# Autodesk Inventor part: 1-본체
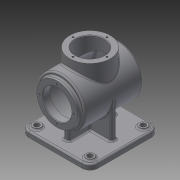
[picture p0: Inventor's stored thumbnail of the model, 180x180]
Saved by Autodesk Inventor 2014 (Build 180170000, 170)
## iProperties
Created: 2015-07
Part Number: 1-본체
Material: 일반
Document SubType Name: Modeling
Designer: Owner
Density: 1 g/cm^3
Appearance: 기본값
Author: Owner
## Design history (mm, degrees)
sketch "스케치1"
  geometry: C1 r 45 at (0, 0); 1 further point
  constraints: 1 centre point, 1 coincident
  dimensions: "d0" = 90 diameter of C1
extrude "돌출1" new body sketch "스케치1" stored distance "d1" = 110; taper "d2" = 0 deg
sketch "스케치2"
  geometry: C1 r 45 at (0, 0) reference; C2 r 38 at (0, 0)
  constraints: 1 centre point, 1 coincident
  dimensions: "d3" = 76 diameter of C2
extrude "돌출2" join sketch "스케치2" distance "d4" = 7; taper "d5" = 0 deg
node "작업 평면1"
sketch "스케치3"
  geometry: L1 (-65, 65)-(65, 65); L2 (65, 65)-(65, -65); L3 (65, -65)-(-65, -65); L4 (-65, -65)-(-65, 65); 3 further points
  constraints: 8 end point, 2 midpoint, 2 parallel, 1 horizontal, 1 horizontal alignment, 1 perpendicular, 1 vertical alignment
  dimensions: "d7" = 130 distance of L2.end L3.end; "d8" = 130 distance of L3.end L1.start
extrude "돌출3" join sketch "스케치3" distance "d9" = 10; taper "d10" = 0 deg
sketch "스케치4"
  geometry: L1 (-65, 65)-(-65, -65) reference; L2 (-45, 5)-(-5, 5); L3 (-5, 5)-(-5, 45); L4 (-5, 45)-(5, 45); L5 (5, 45)-(5, 5); L6 (5, 5)-(45, 5); L7 (45, 5)-(45, -5); L8 (45, -5)-(5, -5); L9 (5, -5)-(5, -45); L10 (5, -45)-(-5, -45); L11 (-5, -45)-(-5, -5); L12 (-5, -5)-(-45, -5); L13 (-45, -5)-(-45, 5); 4 further points
  constraints: 24 end point, 8 parallel, 7 equal length, 3 midpoint, 2 collinear, 2 perpendicular, 2 vertical alignment, 1 horizontal alignment
  dimensions: "d11" = 10 distance of L3.end L4.end; "d12" = 90 distance between parallel lines of L7 L13
extrude "돌출4" join sketch "스케치4" stored distance "d13" = 10; taper "d14" = 0 deg
sketch "스케치5"
  geometry: C1 r 7.5 at (-50, 50); C2 r 7.5 at (-50, -50); C3 r 7.5 at (50, -50); C4 r 7.5 at (50, 50); 1 further point
  constraints: 4 centre point, 2 horizontal alignment, 2 vertical alignment
  dimensions: "d15" = 15 diameter of C1; "d16" = 15 diameter of C2; "d17" = 15 diameter of C3; "d18" = 15 diameter of C4; "d19" = 100 distance of C4.centre C1.centre; "d20" = 50 horizontal distance of C4.centre point (0, 0); "d21" = 100 distance of C2.centre C1.centre; "d22" = 50 horizontal distance of point (0, 0) C1.centre
extrude "돌출5" join sketch "스케치5" distance "d23" = 3; taper "d24" = 0 deg
hole "구멍1" diameter "d27" = 10; stored, may be unused: countersink angle "d31" = 90 deg, drill point angle "d33" = 118 deg; dims "d25" = 10, "d26" = 10, "d28" = 6, "d29" = 4, "d30" = 2, "d32" = 8
hole "구멍2" diameter "d36" = 10; stored, may be unused: countersink angle "d40" = 90 deg, drill point angle "d42" = 118 deg; dims "d34" = 10, "d35" = 10, "d37" = 6, "d38" = 4, "d39" = 2, "d41" = 8
hole "구멍3" diameter "d45" = 10; stored, may be unused: countersink angle "d49" = 90 deg, drill point angle "d51" = 118 deg; dims "d43" = 10, "d44" = 10, "d46" = 6, "d47" = 4, "d48" = 2, "d50" = 8
hole "구멍4" diameter "d54" = 10; stored, may be unused: countersink angle "d58" = 90 deg, drill point angle "d60" = 118 deg; dims "d52" = 10, "d53" = 10, "d55" = 6, "d56" = 4, "d57" = 2, "d59" = 8
hole "구멍5" diameter "d63" = 54; stored, may be unused: countersink angle "d67" = 90 deg, drill point angle "d69" = 0 deg; dims "d61" = 10, "d62" = 10, "d64" = 6, "d65" = 4, "d66" = 2, "d68" = 14
hole "구멍6" diameter "d72" = 80; stored, may be unused: countersink angle "d76" = 90 deg, drill point angle "d78" = 0 deg; dims "d73" = 6, "d74" = 4, "d75" = 2, "d77" = 96, "d110" = 10, "d111" = 10
node "작업 평면2"
sketch "스케치7"
  geometry: C1 r 38 at (0, 0); 1 further point
  constraints: 1 centre point, 1 coincident
  dimensions: "d80" = 76 diameter of C1
extrude "돌출6" join sketch "스케치7" stored distance "d81" = 3; taper "d82" = 0 deg
sketch "스케치8"
  geometry: C1 r 38 at (0, 0) reference; C2 r 27 at (0, 0)
  constraints: 1 centre point, 1 coincident
  dimensions: "d83" = 54 diameter of C2
extrude "돌출7" cut sketch "스케치8" stored distance "d84" = 3; taper "d85" = 0 deg
sketch "스케치9"
  geometry: C1 r 27 at (0, 0) reference; 1 further point
  constraints: 1 vertical alignment
  dimensions: "d86" = 32 distance of C1.centre point (0, 32)
hole "구멍7" sketch "스케치9" at (0, 32) diameter "d87" = 3.242; stored, may be unused: countersink angle "d91" = 90 deg, drill point angle "d93" = 118 deg; dims "d88" = 8, "d89" = 4, "d90" = 2, "d92" = 10
sketch "스케치10"
  geometry: C1 r 27 at (0, 0) reference; 1 further point
  constraints: 1 horizontal alignment
  dimensions: "d97" = 32 distance of C1.centre point (32, 0)
hole "구멍8" sketch "스케치10" at (32, 0) diameter "d98" = 3.242; stored, may be unused: countersink angle "d102" = 90 deg, drill point angle "d104" = 118 deg; dims "d99" = 8, "d100" = 4, "d101" = 2, "d103" = 10
sketch "스케치11"
  geometry: C1 r 45 at (0, 0) reference; 1 further point
  constraints: 1 coincident, 1 other
extrude "돌출8" join sketch "스케치11" distance "d108" = 0.5; taper "d109" = 0 deg
fillet "모깎기1" dims "d112" = 15
chamfer "모따기1" distance "d113" = 1; stored, may be unused: second distance "d114" = 2, angle "d115" = 45 deg
fillet "모깎기2" dims "d116" = 3
fillet "모깎기3" dims "d117" = 3
fillet "모깎기4" dims "d118" = 3
fillet "모깎기5" dims "d119" = 3
fillet "모깎기6" dims "d120" = 3
fillet "모깎기7" dims "d121" = 3
fillet "모깎기8" dims "d122" = 3
fillet "모깎기9" dims "d123" = 3
fillet "모깎기10" dims "d124" = 3
node "솔리드1"
pattern_circular "원형 패턴1" dims angle "d95" = 360 deg
pattern_circular "원형 패턴2" dims angle "d106" = 360 deg
other parameters: "d6" = -78
